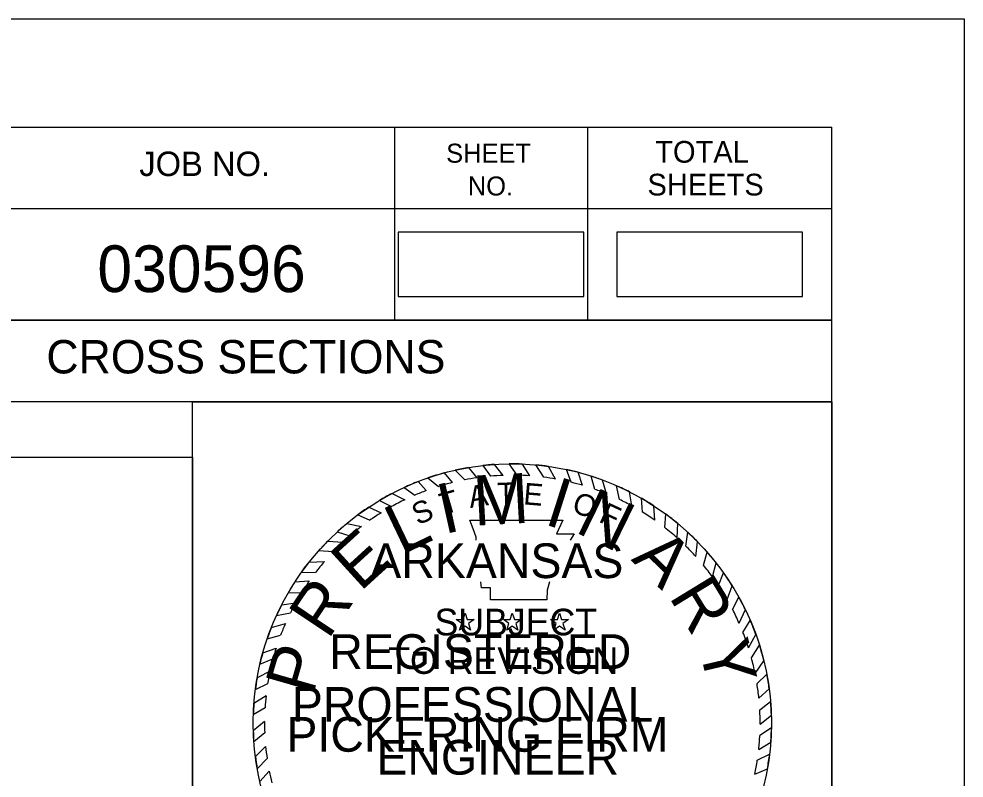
# Model space of a CAD drawing. Extents: x 1368910 to 1369601, y 380116 to 380950.
# Drawn here: x 1369209.17 to 1369243.18, y 380709.8 to 380737.11 of the extents above; entities that cross this region are included whole.
import ezdxf

# ---------------------------------------------------------------- set-up
doc = ezdxf.new("R2010")
doc.units = 0
for name, color, linetype in [('Notes', 7, 'Continuous'), ('R_Border', 7, 'Continuous'), ('R_Border Notes', 7, 'Continuous'), ('R_No Plot', 7, 'Continuous'), ('STAMP_PE_SEAL-INFO', 7, 'Continuous'), ('STAMP_PE_TXT', 7, 'Continuous'), ('STAMP_PRELIMINARY', 7, 'Continuous')]:
    doc.layers.add(name, color=color, linetype=linetype)

msp = doc.modelspace()

# ---------------------------------------------------------------- linework, layer by layer
at = {"layer": 'Notes'}
for points in [[(1369222.812, 380727.123), (1369229.495, 380727.123), (1369229.495, 380729.434), (1369222.812, 380729.434)], [(1369230.682, 380727.123), (1369237.365, 380727.123), (1369237.365, 380729.434), (1369230.682, 380729.434)]]:
    msp.add_lwpolyline(points, close=True, dxfattribs=at)
at = {"layer": 'R_Border'}
for p, q in [((1368922.244, 380733.219), (1369238.424, 380733.219)), ((1369222.684, 380733.219), (1369222.684, 380726.279)), ((1369229.624, 380733.219), (1369229.624, 380726.279)), ((1369238.424, 380527.759), (1369238.424, 380733.219)), ((1369238.424, 380730.279), (1369195.324, 380730.279)), ((1369238.424, 380730.299), (1369238.424, 380730.299)), ((1369238.424, 380726.279), (1369195.324, 380726.279)), ((1369198.284, 380726.279), (1369238.424, 380726.279)), ((1369238.424, 380723.339), (1369175.784, 380723.339))]:
    msp.add_line(p, q, dxfattribs=at)
at = {"layer": 'R_No Plot'}
for points in [[(1368909.836, 380737.113), (1369243.176, 380737.113), (1369243.176, 380523.776), (1368909.836, 380523.776)], [(1369236.424, 380632.489), (1368924.244, 380632.489), (1368924.244, 380731.219), (1369173.784, 380731.219), (1369173.784, 380721.339), (1369191.324, 380721.339), (1369215.424, 380721.339), (1369215.424, 380699.006), (1369236.424, 380699.006)], [(1368924.244, 380731.219), (1369173.784, 380731.219), (1369173.784, 380721.339), (1369191.324, 380721.339), (1369215.424, 380721.339), (1369215.424, 380699.006), (1369236.424, 380699.006), (1369236.424, 380529.759), (1368924.244, 380529.759)], [(1369215.424, 380723.339), (1369238.424, 380723.339), (1369238.424, 380699.006), (1369215.424, 380699.006)]]:
    msp.add_lwpolyline(points, close=True, dxfattribs=at)
at = {"layer": 'STAMP_PE_SEAL-INFO'}
for p, q in [((1369225.86, 380721.043), (1369226.141, 380720.66)), ((1369226.595, 380720.689), (1369226.283, 380721.082)), ((1369227.093, 380720.693), (1369226.815, 380721.103)), ((1369227.551, 380720.673), (1369227.293, 380721.097)), ((1369228.057, 380720.622), (1369227.765, 380721.066)), ((1369224.474, 380720.776), (1369224.762, 380720.429)), ((1369224.862, 380720.873), (1369225.218, 380720.53)), ((1369225.344, 380720.969), (1369225.643, 380720.602)), ((1369228.483, 380720.557), (1369228.225, 380721.013)), ((1369229.045, 380720.439), (1369228.871, 380720.898)), ((1369229.447, 380720.33), (1369229.287, 380720.799)), ((1369223.535, 380720.466), (1369223.83, 380720.141)), ((1369223.883, 380720.594), (1369224.264, 380720.289)), ((1369229.898, 380720.184), (1369229.757, 380720.663)), ((1369230.317, 380720.024), (1369230.172, 380720.52)), ((1369222.597, 380720.039), (1369223.06, 380719.814)), ((1369223.028, 380720.251), (1369223.417, 380719.976)), ((1369230.778, 380719.818), (1369230.675, 380720.316)), ((1369231.224, 380719.589), (1369231.137, 380720.098)), ((1369222.149, 380719.788), (1369222.581, 380719.565)), ((1369231.611, 380719.363), (1369231.572, 380719.863)), ((1369221.762, 380719.545), (1369222.204, 380719.342)), ((1369232.046, 380719.076), (1369232.015, 380719.591)), ((1369221.341, 380719.278), (1369221.797, 380719.073)), ((1369225.397, 380719.073), (1369228.741, 380719.073)), ((1369225.518, 380718.765), (1369225.397, 380719.073)), ((1369228.741, 380719.073), (1369228.516, 380718.581)), ((1369232.406, 380718.809), (1369232.441, 380719.296)), ((1369220.965, 380718.951), (1369221.494, 380718.85)), ((1369225.622, 380718.468), (1369225.518, 380718.765)), ((1369232.853, 380718.437), (1369232.873, 380718.959)), ((1369220.285, 380718.327), (1369220.83, 380718.286)), ((1369220.621, 380718.651), (1369221.08, 380718.512)), ((1369225.629, 380718.353), (1369225.622, 380718.468)), ((1369228.516, 380718.581), (1369229.148, 380718.581)), ((1369229.148, 380718.581), (1369229.003, 380718.353)), ((1369233.166, 380718.144), (1369233.235, 380718.643)), ((1369219.963, 380717.983), (1369220.484, 380717.944)), ((1369233.525, 380717.771), (1369233.591, 380718.297)), ((1369233.798, 380717.455), (1369233.935, 380717.926)), ((1369219.617, 380717.571), (1369220.166, 380717.594)), ((1369234.122, 380717.038), (1369234.258, 380717.537)), ((1369219.339, 380717.202), (1369219.844, 380717.197)), ((1369234.342, 380716.722), (1369234.52, 380717.186)), ((1369219.104, 380716.858), (1369219.62, 380716.891)), ((1369225.82, 380716.644), (1369225.794, 380716.862)), ((1369226.135, 380716.644), (1369225.82, 380716.644)), ((1369226.135, 380716.214), (1369226.135, 380716.644)), ((1369228.258, 380716.862), (1369228.18, 380716.552)), ((1369234.65, 380716.225), (1369234.833, 380716.716)), ((1369218.858, 380716.457), (1369219.347, 380716.477)), ((1369228.18, 380716.552), (1369228.164, 380716.214)), ((1369234.85, 380715.859), (1369235.076, 380716.303)), ((1369218.627, 380716.033), (1369219.125, 380716.098)), ((1369228.164, 380716.214), (1369226.135, 380716.214)), ((1369218.439, 380715.645), (1369218.942, 380715.748)), ((1369235.081, 380715.375), (1369235.307, 380715.859)), ((1369218.255, 380715.212), (1369218.759, 380715.358)), ((1369235.221, 380715.037), (1369235.485, 380715.471)), ((1369218.105, 380714.806), (1369218.589, 380714.942)), ((1369235.416, 380714.488), (1369235.687, 380714.963)), ((1369217.948, 380714.303), (1369218.426, 380714.472)), ((1369235.524, 380714.124), (1369235.818, 380714.576)), ((1369217.844, 380713.895), (1369218.314, 380714.088)), ((1369235.657, 380713.565), (1369235.976, 380714.012)), ((1369218.208, 380713.649), (1369217.743, 380713.4)), ((1369235.726, 380713.185), (1369236.079, 380713.538)), ((1369218.122, 380713.19), (1369217.677, 380712.968)), ((1369235.792, 380712.676), (1369236.165, 380713.012)), ((1369218.063, 380712.755), (1369217.627, 380712.474)), ((1369235.824, 380712.258), (1369236.215, 380712.55)), ((1369218.027, 380712.33), (1369217.606, 380712.073)), ((1369235.837, 380711.74), (1369236.242, 380712.061)), ((1369218.01, 380711.836), (1369217.605, 380711.501)), ((1369235.826, 380711.335), (1369236.245, 380711.612)), ((1369218.017, 380711.429), (1369217.626, 380711.105)), ((1369218.05, 380710.934), (1369217.679, 380710.577)), ((1369235.786, 380710.828), (1369236.22, 380711.085)), ((1369218.102, 380710.505), (1369217.748, 380710.132)), ((1369235.736, 380710.44), (1369236.179, 380710.659)), ((1369218.181, 380710.046), (1369217.841, 380709.678)), ((1369235.645, 380709.94), (1369236.1, 380710.135))]:
    msp.add_line(p, q, dxfattribs=at)
for radius, start, end in [(9.323, 93.9381, 96.5517), (9.323, 87.7298, 90.6707), (9.323, 81.9732, 84.8236), (9.323, 105.2339, 109.0352), (9.323, 99.7525, 102.7765), (9.323, 75.3125, 77.9426), (9.323, 111.3124, 114.7026), (8.914, 104.0352, 107.3615), (8.914, 98.258, 101.0329), (8.914, 92.1102, 95.0367), (8.914, 85.9628, 88.9097), (8.914, 79.9264, 82.696), (8.914, 73.5575, 76.2314), (9.323, 69.6061, 72.3058), (9.323, 117.6544, 120.8099), (8.914, 110.3086, 113.1659), (8.914, 67.6248, 70.504), (9.323, 63.1329, 66.2704), (8.914, 115.6869, 119.1583), (8.914, 61.1558, 64.3784), (9.323, 56.9003, 60.0942), (9.323, 123.6199, 126.5906), (8.914, 54.9238, 58.2702), (8.914, 121.9746, 125.11), (9.323, 50.3492, 53.7159), (9.323, 129.7326, 132.5376), (8.914, 127.5297, 130.9683), (8.914, 48.3016, 52.0395), (9.323, 135.4021, 138.3031), (9.323, 44.3405, 47.3929), (8.914, 133.1331, 136.2562), (8.914, 42.2212, 45.5512), (9.323, 38.1247, 41.2316), (9.323, 141.6056, 144.4486), (8.914, 139.301, 142.5873), (8.914, 36.135, 39.5311), (9.323, 31.9614, 35.4294), (9.323, 147.0072, 149.899), (8.914, 145.0197, 148.2104), (8.914, 29.9032, 33.6645), (9.323, 25.9391, 29.0125), (9.323, 152.864, 155.5189), (8.914, 151.0315, 153.573), (8.914, 23.7732, 27.2211), (8.914, 156.3402, 159.2319), (9.323, 19.9538, 23.3141), (9.323, 158.4077, 161.0701), (8.914, 17.6802, 21.4251), (9.323, 164.3068, 166.894), (8.914, 162.4331, 165.0013), (9.323, 13.8421, 17.4447), (8.914, 11.5444, 15.2364), (8.914, 167.9048, 170.9039), (9.323, 170.0003, 172.6878), (9.323, 7.5852, 10.8621), (8.914, 5.7599, 9.0606), (8.914, 173.73, 176.4734), (9.323, 1.7215, 4.7268), (9.323, 175.7409, 178.2066), (8.914, 359.7329, 3.0639), (8.914, 179.6454, 182.2633), (9.323, 355.7156, 358.9569), (9.323, 181.7251, 184.1626), (8.914, 353.8632, 357.1274), (8.914, 185.4539, 188.234), (9.323, 187.4204, 190.1927), (9.323, 349.8305, 353.0885), (8.914, 348.0778, 351.3435), (8.914, 191.2274, 193.9858)]:
    msp.add_arc((1369226.924, 380711.781), radius, start, end, dxfattribs=at)
at = {"layer": 'STAMP_PE_TXT'}
for p, q in [((1369225.15, 380715.497), (1369225.226, 380715.73)), ((1369225.226, 380715.73), (1369225.301, 380715.497)), ((1369226.848, 380715.497), (1369226.924, 380715.73)), ((1369226.924, 380715.73), (1369226.999, 380715.497)), ((1369228.546, 380715.497), (1369228.622, 380715.73)), ((1369228.622, 380715.73), (1369228.697, 380715.497)), ((1369225.103, 380715.353), (1369224.905, 380715.497)), ((1369224.905, 380715.497), (1369225.15, 380715.497)), ((1369225.027, 380715.12), (1369225.103, 380715.353)), ((1369225.226, 380715.264), (1369225.027, 380715.12)), ((1369225.424, 380715.12), (1369225.226, 380715.264)), ((1369225.301, 380715.497), (1369225.547, 380715.497)), ((1369225.547, 380715.497), (1369225.348, 380715.353)), ((1369225.348, 380715.353), (1369225.424, 380715.12)), ((1369226.801, 380715.353), (1369226.603, 380715.497)), ((1369226.603, 380715.497), (1369226.848, 380715.497)), ((1369226.725, 380715.12), (1369226.801, 380715.353)), ((1369226.924, 380715.264), (1369226.725, 380715.12)), ((1369227.122, 380715.12), (1369226.924, 380715.264)), ((1369226.999, 380715.497), (1369227.245, 380715.497)), ((1369227.245, 380715.497), (1369227.046, 380715.353)), ((1369227.046, 380715.353), (1369227.122, 380715.12)), ((1369228.499, 380715.353), (1369228.301, 380715.497)), ((1369228.301, 380715.497), (1369228.546, 380715.497)), ((1369228.423, 380715.12), (1369228.499, 380715.353)), ((1369228.622, 380715.264), (1369228.423, 380715.12)), ((1369228.82, 380715.12), (1369228.622, 380715.264)), ((1369228.697, 380715.497), (1369228.943, 380715.497)), ((1369228.943, 380715.497), (1369228.744, 380715.353)), ((1369228.744, 380715.353), (1369228.82, 380715.12))]:
    msp.add_line(p, q, dxfattribs=at)
at = {"layer": 'STAMP_PRELIMINARY'}
msp.add_circle((1369226.924, 380711.781), 9.323, dxfattribs=at)

# ---------------------------------------------------------------- texts
at = {"layer": 'R_Border'}
for s, height, p in [('SHEET', 0.684, (1369224.544, 380731.939)), ('TOTAL', 0.7819, (1369232.064, 380731.939)), ('JOB NO.', 0.8792, (1369213.504, 380731.459)), ('NO.', 0.684, (1369225.324, 380730.759)), ('SHEETS', 0.7819, (1369231.784, 380730.759))]:
    msp.add_text(s, height=height, dxfattribs=at).set_placement(p)
at = {"layer": 'R_Border Notes'}
for s, height, p in [('030596', 1.68, (1369211.996, 380727.284)), ('CROSS SECTIONS', 1.2, (1369210.162, 380724.357))]:
    msp.add_text(s, height=height, dxfattribs=at).set_placement(p)
at = {"layer": 'STAMP_PE_TXT'}
for s, rotation, p in [('T', 1.8248, (1369226.394, 380719.64)), ('E', 355.2002, (1369227.304, 380719.648)), ('T', 16.311, (1369224.445, 380719.257)), ('A', 9.0679, (1369225.408, 380719.51)), ('O', 342.2506, (1369229.031, 380719.371)), ('S', 23.5541, (1369223.522, 380718.885)), ('F', 335.0075, (1369229.996, 380719.033))]:
    msp.add_text(s, height=0.781, rotation=rotation, dxfattribs=at).set_placement(p)
for s, p in [('ARKANSAS', (1369221.816, 380716.992)), ('REGISTERED', (1369220.34, 380713.722)), ('PROFESSIONAL', (1369218.992, 380711.821)), ('ENGINEER', (1369222.033, 380709.919))]:
    msp.add_text(s, height=1.25, dxfattribs=at).set_placement(p)
at = {"layer": 'STAMP_PRELIMINARY'}
for s, rotation, p in [('M', 3.1074, (1369225.559, 380718.877)), ('I', 12.5248, (1369224.461, 380718.568)), ('I', 342.3164, (1369228.027, 380718.944)), ('N', 333.9382, (1369229.135, 380718.67)), ('L', 25.513, (1369222.932, 380717.809)), ('E', 42.3578, (1369221.45, 380716.478)), ('A', 315.6579, (1369231.168, 380717.645)), ('R', 301.3831, (1369232.536, 380716.331)), ('R', 56.2292, (1369220.294, 380714.745)), ('Y', 283.2593, (1369233.626, 380714.544)), ('P', 73.913, (1369219.745, 380712.722))]:
    msp.add_text(s, height=1.8, rotation=rotation, dxfattribs=at).set_placement(p)
for s, height, p in [('SUBJECT', 0.96, (1369224.124, 380714.931)), ('TO REVISION', 0.96, (1369222.459, 380713.546)), ('PICKERING FIRM', 1.25, (1369218.797, 380710.745))]:
    msp.add_text(s, height=height, dxfattribs=at).set_placement(p)

doc.saveas('drawing.dxf')
